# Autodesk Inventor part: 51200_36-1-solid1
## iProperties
Created: 2010-10
Part Number: 51200_36-1-solid1
Document SubType Name: Modeling
Designer: Administrator
Density: 7.85 g/cm^3
Material: Steel
Mass: 234.365 g
Surface Area: 130.379 cm^2
Volume: 29.8554 cm^3
Author: Administrator
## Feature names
1. Base1
